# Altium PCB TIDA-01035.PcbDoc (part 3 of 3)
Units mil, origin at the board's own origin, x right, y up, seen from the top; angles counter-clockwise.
Board outline 3937.01 x 2952.76 mil, 4 copper layers (Top Layer, GND, PWR, Bottom Layer), stack 79.834 mil thick; 286 components, 165 nets, 861 pads, 352 vias.
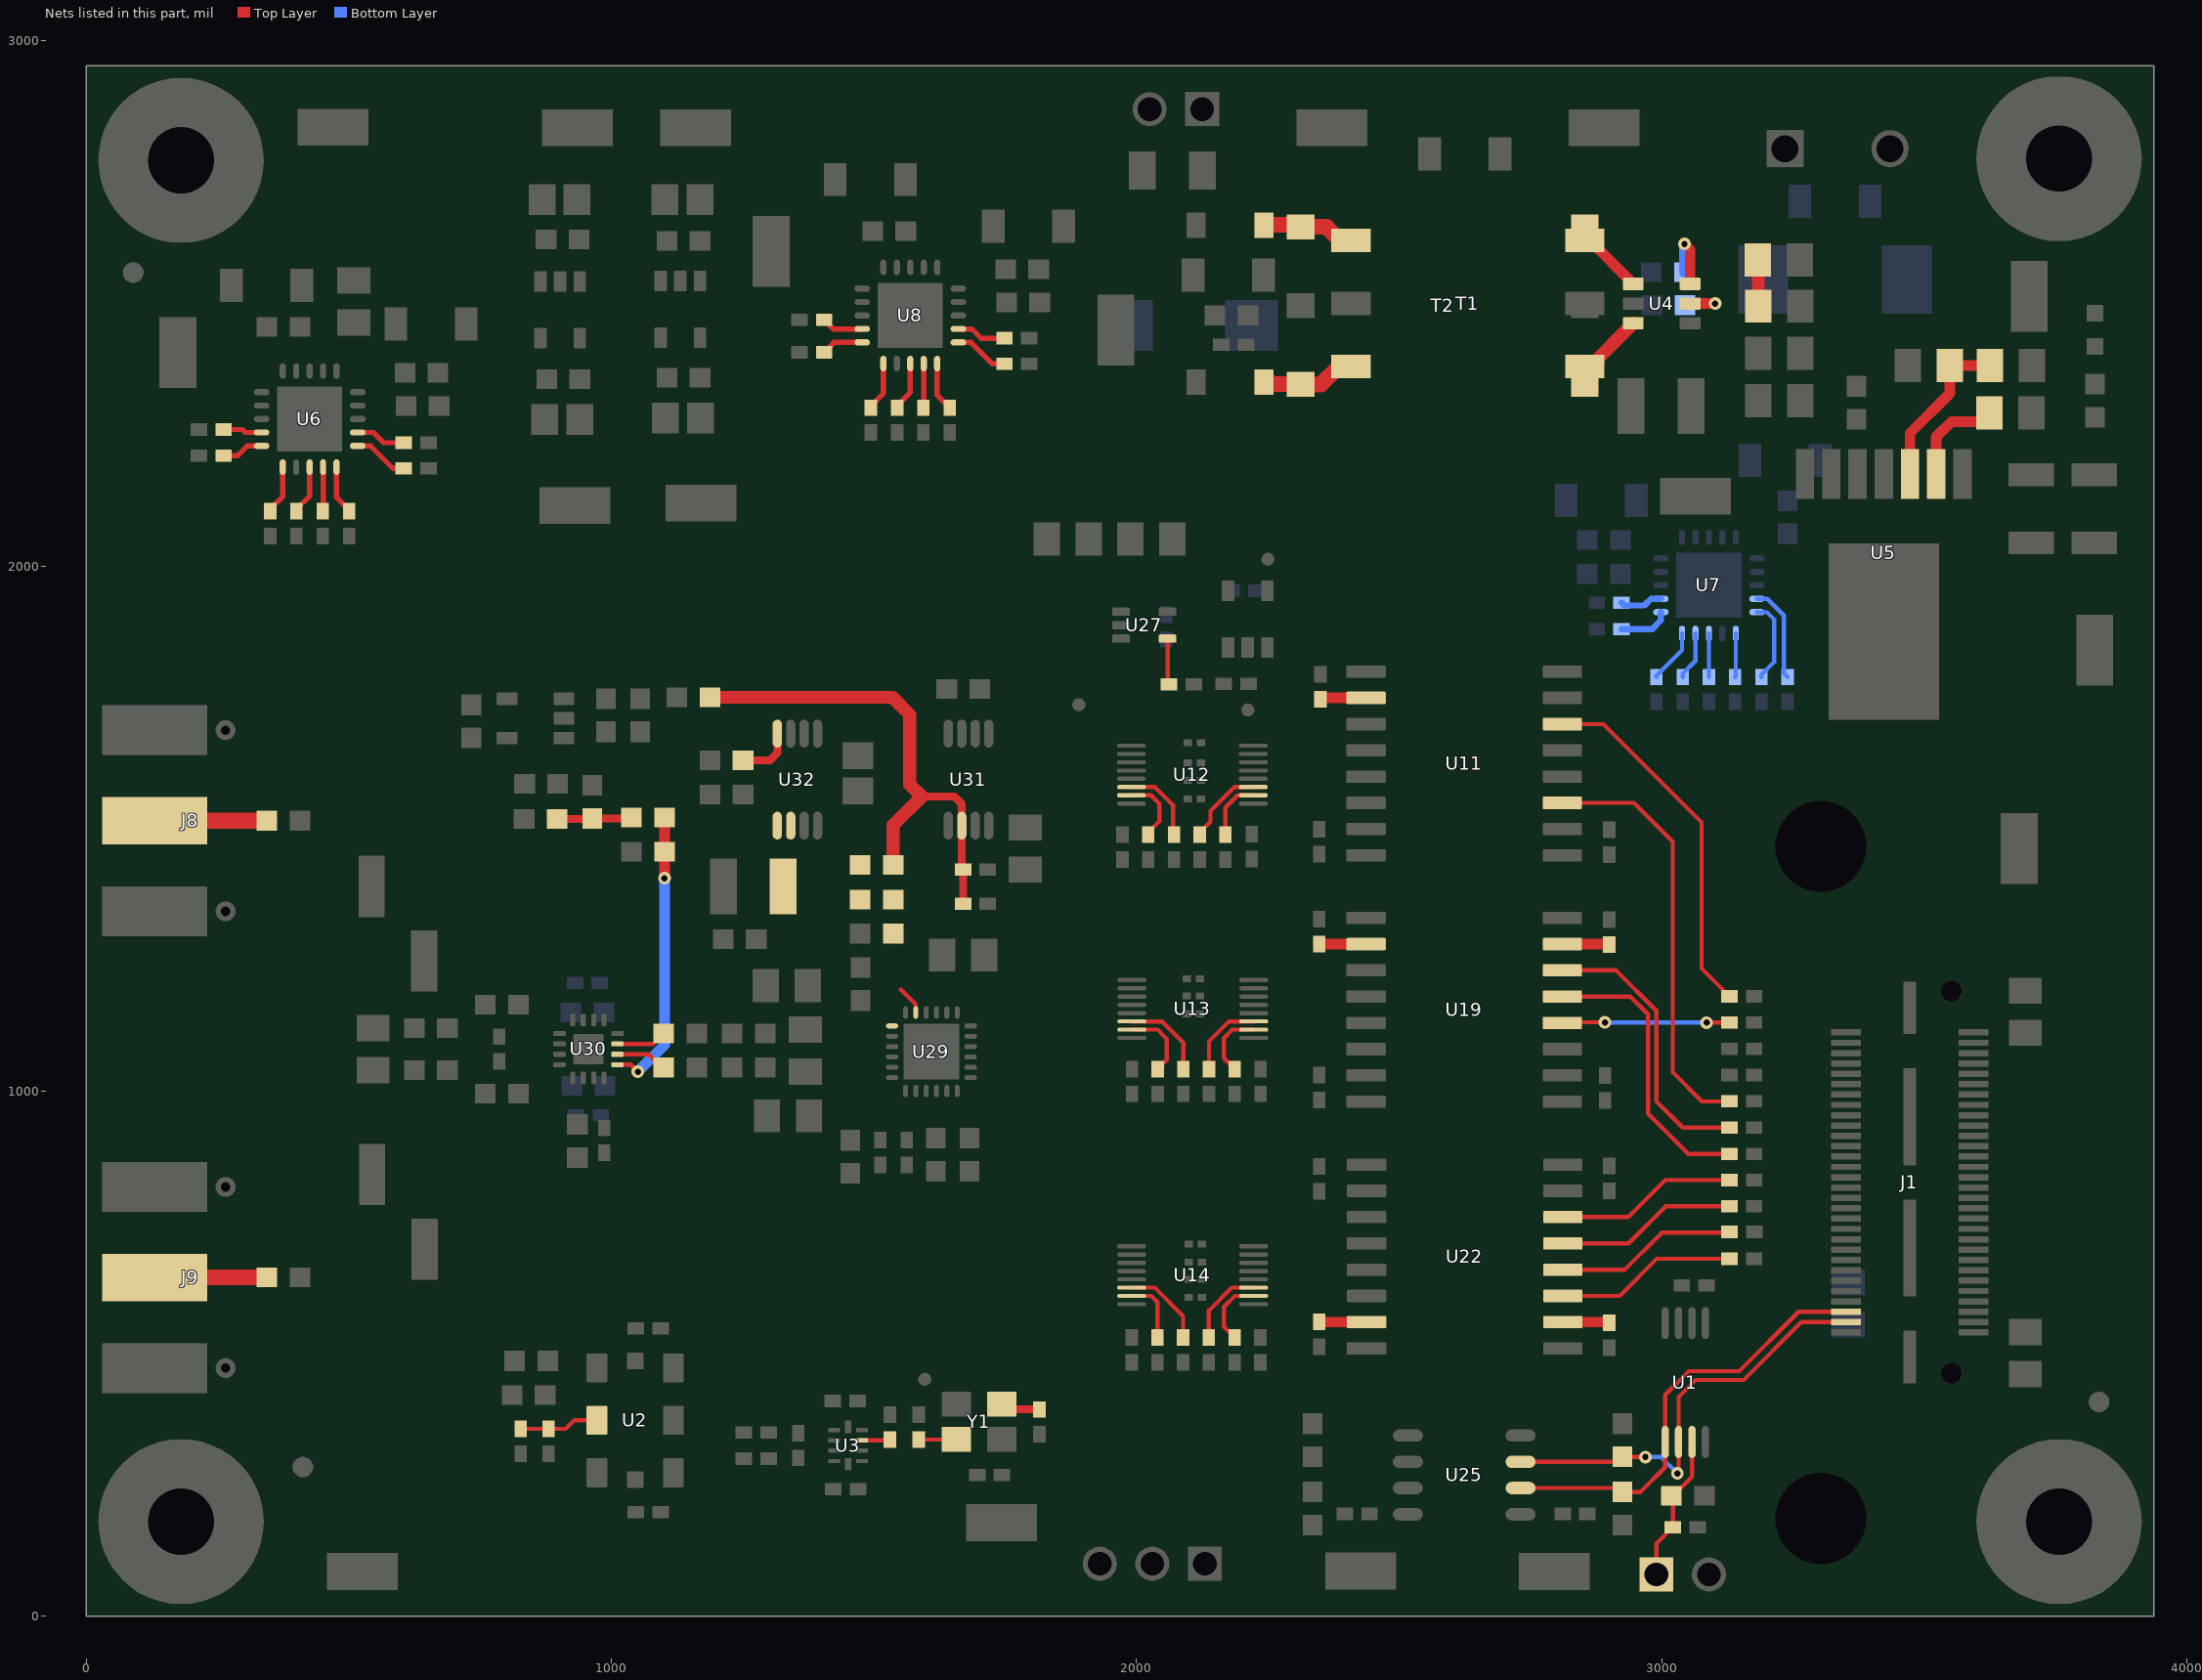
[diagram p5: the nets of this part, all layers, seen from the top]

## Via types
v1: diameter 24, hole 12, Top Layer to Bottom Layer, tented both sides, 324 vias
v2: diameter 19.68, hole 7.87, Top Layer to Bottom Layer, 24 vias
v3: diameter 32, hole 16, Top Layer to Bottom Layer, 4 vias

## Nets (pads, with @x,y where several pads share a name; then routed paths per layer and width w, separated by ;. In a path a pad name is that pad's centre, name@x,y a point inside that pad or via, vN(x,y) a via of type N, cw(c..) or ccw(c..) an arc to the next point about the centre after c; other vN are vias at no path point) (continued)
NetR13_1: R13.1 Y1.1 | length 75.8
  Top Layer w15: Y1.1@1753.15,393.62 R13.1@1815,393.62
  Top Layer w20: Y1.1@1743.31,403.46 Y1.1@1753.15,393.62
NetR14_1: R14.1 Y1.3 | length 71.8
  Top Layer w8: R14.1@1585,336.38 1656.54,336.38 Y1.3@1656.69,336.54
NetR17_1: R17.1 U3.8 | length 53.5
  Top Layer w8: U3.8@1477.09,334.84 1528.46,334.84 R17.1@1530,336.38
NetR18_1: R18.1 U12.3 | length 154.2
  Top Layer w8: R18.1@2120.18,1488.39 2120.18,1492.77 2140.68,1513.27 2140.68,1533.67 2186.16,1579.15 U12.3@2222.32,1579.15
NetR20_2: R20.2 R21.2 U2.2@972.17,373 | length 151.9
  Top Layer w8: R21.2@827,356.62 R20.2@880,356.62 912.62,356.62 929,373 U2.2@972.17,373
NetR24_1: R24.1 R34.2 U5.3 | length 288.9
  Top Layer w20: U5.3@3473,2175.63 3473,2253 3549,2329 R34.2@3549,2382 3597,2382 ; R34.2@3541,2382 R34.2@3541,2385
NetR26_1: R26.1 U5.2 | length 190.4
  Top Layer w20: U5.2@3523,2175.63 3523,2246 3552,2275 3607,2275 R26.1@3624,2292
NetR27_2: R27.2 U6.4 | length 74.8
  Top Layer w10: R27.2@261.06,2260.06 296.87,2260.06 302.46,2254.47 U6.4@333.53,2254.47
NetR28_2: R28.2 U6.5 | length 80.3
  Top Layer w10: R28.2@261.06,2210.06 287.27,2210.06 306.09,2228.88 U6.5@333.53,2228.88
NetR29_2: R29.2 U6.6 | length 94.1
  Top Layer w10: R29.2@350.06,2104.31 350.06,2108.85 373.88,2132.67 U6.6@373.88,2188.53
NetR30_2: R30.2 U6.8 | length 94.6
  Top Layer w10: R30.2@400.06,2104.31 400.06,2108.85 425.06,2133.85 U6.8@425.06,2188.53
NetR31_1: R31.1 R36.2 | length 88.7
  Top Layer w25: R36.2@3183.21,2583.35 3184,2582.56 R31.1@3184,2495
NetR32_2: R32.2 U6.9 | length 84.5
  Top Layer w10: R32.2@450.06,2104.31 450.65,2104.9 U6.9@450.65,2188.53
NetR33_2: R33.2 U6.10 | length 94.1
  Top Layer w10: U6.10@476.24,2188.53 476.24,2130.69 500.06,2106.87 R33.2@500.06,2104.31
NetR35_2: R35.2 U6.11 | length 105.6
  Top Layer w10: U6.11@516.6,2228.88 541.05,2228.88 583.87,2186.06 R35.2@604.44,2186.06
NetR37_2: R37.2 U6.12 | length 95.9
  Top Layer w10: U6.12@516.6,2254.47 546.46,2254.47 565.87,2235.06 R37.2@604.44,2235.06
NetR41_2: R41.2 U7.4 | length 184.9
  Bottom Layer w8: U7.4@3181.54,1937.76 3201.24,1937.76 3233,1906 3233,1795.62 R41.2@3240,1788.62
NetR42_2: R42.2 U8.4 | length 79.8
  Top Layer w10: R42.2@1405,2469.27 1422.59,2451.68 U8.4@1477.46,2451.68
NetR43_2: R43.2 U7.5 | length 158.2
  Bottom Layer w8: U7.5@3181.54,1912.17 3200.83,1912.17 3214,1899 3214,1817 3190,1793 R43.2@3190,1788.62
NetR44_2: R44.2 U8.5 | length 80.3
  Top Layer w10: R44.2@1405,2407.27 1423.82,2426.08 U8.5@1477.46,2426.08
NetR45_2: R45.2 U7.6 | length 83.7
  Bottom Layer w8: R45.2@3140,1788.62 3141.18,1789.8 U7.6@3141.18,1871.81
NetR46_2: R46.2 U8.6 | length 94.1
  Top Layer w10: R46.2@1494,2301.51 1494,2305 1517.82,2328.82 U8.6@1517.82,2385.73
NetR47_2: R47.2 U7.8 | length 83.2
  Bottom Layer w8: R47.2@3090,1788.62 U7.8@3090,1871.81
NetR48_2: R48.2 U8.8 | length 94.6
  Top Layer w10: R48.2@1544,2301.51 1544,2306 1569,2331 U8.8@1569,2385.73
NetR49_2: R49.2 U7.9 | length 93.3
  Bottom Layer w8: R49.2@3040,1788.62 3040,1795 3064.41,1819.41 U7.9@3064.41,1871.81
NetR50_2: R50.2 U8.9 | length 84.5
  Top Layer w10: R50.2@1594,2301.51 1594.59,2302.1 U8.9@1594.59,2385.73
NetR51_2: R51.2 U7.10 | length 103.4
  Bottom Layer w8: R51.2@2990,1788.62 2990,1791 3038.82,1839.82 U7.10@3038.82,1871.81
NetR52_2: R52.2 U8.10 | length 94.1
  Top Layer w10: U8.10@1620.18,2385.73 1620.18,2325.33 R52.2@1644,2301.51
NetR53_2: R53.2 U7.11 | length 97.4
  Bottom Layer w12: R53.2@2923.62,1880 2982,1880 2998.46,1896.46 U7.11@2998.46,1912.17
NetR54_2: R54.2 U8.11 | length 108.7
  Top Layer w10: U8.11@1660.54,2426.08 1684.92,2426.08 1726,2385 R54.2@1745.64,2385 ; R54.2@1748.38,2382.27 R54.2@1745.64,2385 ; R54.2@1748.38,2385 R54.2@1745.64,2385
NetR55_2: R55.2 U7.12 | length 82.2
  Bottom Layer w12: R55.2@2923.62,1930 2928.62,1925 2967,1925 2979.76,1937.76 U7.12@2998.46,1937.76
NetR56_2: R56.2 U8.12 | length 99
  Top Layer w10: U8.12@1660.54,2451.68 1686,2451.68 1703.68,2434 R56.2@1745.64,2434 ; R56.2@1748.38,2431.27 R56.2@1745.64,2434 ; R56.2@1748.38,2434 R56.2@1745.64,2434
NetR59_1: R59.1 U11.10 | length 88.1
  Top Layer w8: R59.1@2350,1746.38 R59.1@2352.62,1749
  Top Layer w20: R59.1@2352.62,1749 U11.10@2436.99,1749
NetR64_2: R64.2 U19.7 | length 89.2
  Top Layer w20: U19.7@2811.01,1280 2899.38,1280 R64.2@2900,1279.38
NetR65_1: R65.1 U19.10 | length 89.1
  Top Layer w20: R65.1@2348,1280.38 2348.38,1280 U19.10@2436.99,1280
NetR69_1: R69.1 U22.10 | length 88.6
  Top Layer w20: U22.10@2812.01,560 2898.62,560 R69.1@2900,558.62
NetR70_2: R70.2 U22.7 | length 90.2
  Top Layer w20: R70.2@2348,560.62 2348.62,560 U22.7@2437.99,560
NetR78_1: R78.1 U30.11 | length 97.3
  Top Layer w8: U30.11@1011.12,1089.84 1078.02,1089.84 1078.68,1089.18 R78.1@1099.5,1110
NetR84_1: R84.1 R85.2 U29.5 U29.7 | length 55.4
  Top Layer w8: 1551,1193 1551.48,1193 1579.54,1164.94 U29.5@1579.54,1149.74
NetR88_1: R88.1 U30.10 | length 98.8
  Top Layer w8: U30.10@1011.12,1070.16 1070.84,1070.16 1096,1045 R88.1@1099.5,1045
NetR94_2: R94.2 R95.2 R96.2 | length 142.8
  Top Layer w15: R94.2@896.5,1518 961.5,1518 R96.2@963,1519.5 1036.51,1519.5 R95.2@1038.01,1521
NetR100_2: R100.2 U32.4 | length 108
  Top Layer w15: R100.2@1250.56,1629.94 1301.94,1629.94 1315.68,1643.68 U32.4@1315.68,1680.88
NetR102_2: R102.2 U27.4 | length 88.1
  Top Layer w8: U27.4@2059,1861.82 2059,1777.87 R102.2@2061.96,1774.91
NetR103_1: R103.1 U4.5 | length 106.6
  Top Layer w20: U4.5@3054.13,2500 v1(3102,2500)
  Bottom Layer w20: R103.1@3044.5,2497 3047.5,2500 v1(3102,2500)
NetR104_2: R104.2 U4.6 | length 134
  Top Layer w20: v1(3043.5,2613.5) 3054.13,2602.86 U4.6@3054.13,2537.4
  Bottom Layer w20: R104.2@3043.5,2560 v1(3043.5,2613.5)
NetR105_1: R105.1 U12.2 | length 114.6
  Top Layer w8: R105.1@2169.18,1488.39 2169.18,1540.25 2192.33,1563.4 U12.2@2222.32,1563.4
NetR106_2: R106.2 U12.15 | length 127.7
  Top Layer w8: U12.15@1990.04,1563.4 2027.55,1563.4 2043.18,1547.77 2043.18,1513.77 2022.18,1492.77 R106.2@2022.18,1488.39
NetR107_2: R107.2 U12.14 | length 150.6
  Top Layer w8: U12.14@1990.04,1579.15 2034.8,1579.15 2069.24,1544.71 2069.24,1490.33 R107.2@2071.18,1488.39
NetR108_1: R108.1 U13.2 | length 131.2
  Top Layer w8: R108.1@2187.04,1042.02 2166.18,1062.88 2166.18,1100.85 2182.36,1117.03 U13.2@2223.18,1117.03
NetR109_2: R109.2 U13.15 | length 138.3
  Top Layer w8: U13.15@1990.9,1117.03 2039.92,1117.03 2057.18,1099.77 2057.18,1059.17 R109.2@2040.04,1042.02
NetR110_2: R110.2 U13.14 | length 165
  Top Layer w8: U13.14@1990.9,1132.78 2048.17,1132.78 2089.04,1091.91 R110.2@2089.04,1042.02
NetR111_2: R111.2 U13.3 | length 153.6
  Top Layer w8: R111.2@2138.04,1042.02 2138.04,1094.63 2176.19,1132.78 U13.3@2223.18,1132.78
NetR112_2: R112.2 U14.15 | length 121.3
  Top Layer w8: U14.15@1990.54,609.9 2028.05,609.9 2039.68,598.27 R112.2@2039.68,530.89
NetR113_2: R113.2 U14.14 | length 161
  Top Layer w8: U14.14@1990.54,625.65 2034.3,625.65 2088.68,571.27 R113.2@2088.68,530.89
NetR114_2: R114.2 U14.2 | length 131.8
  Top Layer w8: R114.2@2186.68,530.89 2166.18,551.39 2166.18,588.85 2187.23,609.9 U14.2@2222.82,609.9
NetR115_2: R115.2 U14.3 | length 154.5
  Top Layer w8: R115.2@2137.68,530.89 2137.68,582.27 2181.06,625.65 U14.3@2222.82,625.65
NISO_SCL: J1.58 R74.1 U1.6 U25.3 | length 839.8
  Top Layer w8: U25.3@2731.28,294 2915.5,294 R74.1@2925,303.5 2968.5,303.5 v1(2969,303) ; v1(3030,272) 3032.2,274.2 U1.6@3032.2,331.81 3032.2,417.2 3065,450 3156,450 3266.15,560.15 J1.58@3351,560.15
  Bottom Layer w8: v1(2969,303) 2999,303 v1(3030,272)
NISO_SDA: J1.56 R72.1 U1.5 U25.2 | length 845.9
  Top Layer w8: U25.2@2731.28,244 2917.5,244 R72.1@2925,236.5 2959.5,236.5 3006.61,283.61 U1.5@3006.61,331.81 3006.61,421.61 3051.65,466.65 3147.65,466.65 3260.85,579.85 J1.56@3351,579.85
REFIN_ADS8900B: R90.1 R93.2 R97.2 R98.1 U31.6 | length 976.1
  Top Layer w15: 1591,1561 1653,1561 1667.06,1546.94 U31.6@1667.06,1505.68 1667.06,1424.32 R93.2@1669.38,1422 R90.1@1669.38,1357
  Top Layer w25: R97.2@1187.5,1750 1535,1750 1568,1717 1568,1584 1591,1561 1536.5,1506.5 R98.1@1536.5,1440
REFIN_ADS9110: C98.2 R84.2 R98.2 U32.5 U32.6
RVS: R8.1 U19.5 | length 552.8
  Top Layer w8: U19.5@2811.01,1180 2940.37,1180 2974,1146.37 2974,957 3050.45,880.55 R8.1@3128.88,880.55
SCLK: R5.1 U11.3 | length 810.5
  Top Layer w8: U11.3@2811.01,1549 2947,1549 3021,1475 3021,1036 3076.45,980.55 R5.1@3128.88,980.55
SDI: R2.1 U19.4 | length 318.5
  Top Layer w8: U19.4@2811.01,1130 2812.01,1131 v1(2892,1131) ; v1(3085.55,1130.55) R2.1@3128.88,1130.55
  Bottom Layer w8: v1(2892,1131) 2892.45,1130.55 v1(3085.55,1130.55)
SDO0: R9.1 U22.14 | length 346.1
  Top Layer w8: U22.14@2812.01,760 2936,760 3006.55,830.55 R9.1@3128.88,830.55
SDO1: R10.1 U22.13 | length 346.1
  Top Layer w8: U22.13@2812.01,710 2937,710 3007.55,780.55 R10.1@3128.88,780.55
SDO2: R11.1 U22.12 | length 346.1
  Top Layer w8: U22.12@2812.01,660 2930,660 3000.55,730.55 R11.1@3128.88,730.55
SDO3: R12.1 U22.11 | length 346.1
  Top Layer w8: U22.11@2812.01,610 2920,610 2990.55,680.55 R12.1@3128.88,680.55
SRESETN: R1.1 U11.6 | length 695.8
  Top Layer w8: U11.6@2811.01,1699 2889,1699 3076,1512 3076,1233.42 R1.1@3128.88,1180.55
SYSCLK: R7.1 U19.6 | length 542.9
  Top Layer w8: U19.6@2811.01,1230 2913,1230 2990,1153 2990,980.63 3040.08,930.55 R7.1@3128.88,930.55
TX1: T1.1 T2.1 U4.3 | length 126.5
  Top Layer w25: T1.1@2853.64,2379.92 2863.19,2379.92 U4.3@2945.87,2462.6
TX3: T1.3 T2.3 U4.1 | length 126.5
  Top Layer w20: T1.3@2853.64,2620.08 2863.19,2620.08 U4.1@2945.87,2537.4
TX4: D3.2 T1.4 T2.4 | length 181.9
  Top Layer w30: D3.2@2242.47,2650.35 T2.4@2317.79,2650.35 ; T2.4@2312.53,2646 2362,2646 2387.92,2620.08 T1.4@2408.36,2620.08
TX6: D1.2 T1.6 T2.6 | length 167.1
  Top Layer w30: D1.2@2255.26,2350.35 2259.26,2346.35 T2.6@2310.79,2346.35 ; T2.6@2312.53,2346 2351,2346 2384.92,2379.92 T1.6@2408.36,2379.92
VIN+: J9.1 R86.1 | length 213.5
  Top Layer w30: J9.1@130,645 R86.1@343.5,645
VIN-: J8.1 R80.1 | length 213.5
  Top Layer w30: J8.1@130,1515 R80.1@343.5,1515
VOCM: C100.1 R95.1 U30.9 | length 549.6
  Top Layer w8: U30.9@1011.12,1050.47 1036.53,1050.47 v1(1050,1037)
  Top Layer w15: v1(1100.94,1405.43) v1@1101,1405.5
  Top Layer w20: v1@1101,1405.5 C100.1@1101,1456 R95.1@1101,1521
  Bottom Layer w20: v1(1050,1037) 1100.94,1087.94 v1(1100.94,1405.43)
WP1: C3.2 J2.1 R6.1 U1.7 | length 284.5
  Top Layer w8: J2.1@2990,79.5 2990,138.12 C3.2@3021.38,169.5 3021.38,226.63 R6.1@3018.5,229.5 3021.44,229.5 3057.8,265.85 U1.7@3057.8,331.81
pads on no net: FID1.1 FID2.1 FID3.1 FID4.1 FID5.1 FID6.1 H1.1 H2.1 H3.1 H4.1 H5.0 H6.0 H7.0 H8.0 H13. H14. J1.2 J1.3 J1.4 J1.5 J1.6 J1.7 J1.8 J1.9 J1.10 J1.11 J1.12 J1.13 J1.14 J1.15 J1.17 J1.19 J1.21 J1.23 J1.25 J1.26 J1.27 J1.29 J1.31 J1.33 J1.35 J1.36 J1.37 J1.39 J1.41 J1.43 J1.45 J1.46 J1.47 J1.48 J1.49 J1.51 J1.52 J1.53 J1.54 J1.55 J1.57 J1.MH1 J1.MH2 U2.1@972.17,457.25 U2.1@972.17,488.75 U2.2@972.17,357.25 U2.2@972.17,388.75 U2.3@972.17,257.25 U2.3@972.17,288.75 U2.4@1117.83,257.25 U2.4@1117.83,288.75 U2.5@1117.83,357.25 U2.5@1117.83,388.75 U2.6@1117.83,457.25 U2.6@1117.83,488.75 U3.4 U3.6 U3.9 U6.2 U6.17 U6.18 U6.19 U7.2 U7.17 U7.18 U7.19 U8.2 U8.17 U8.18 U8.19 U9.3 U9.4 U10.3 U10.4 U11.7 U13.5 U13.12 U19.3 U19.14 U21.1 U29.6 U31.1 U31.3 U31.5 U31.7 U31.8

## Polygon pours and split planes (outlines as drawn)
NetC13_1 on Top Layer "Top Layer-No Net" (solid, pour order 63): 2091.79,2903.35 2091.79,2614.35 2081.79,2604.35 1929.79,2604.35 1916.79,2591.35 1916.79,2314.35 1925.79,2305.35 2164.79,2305.35 2170.79,2311.35 2170.79,2474.35 2169.79,2475.35 2169.79,2907.35 2158.79,2918.35 2099.79,2918.35 2091.79,2910.35
AGND_ISO on Top Layer "Top Layer-No Net" (solid, remove dead copper, pour order 71): 1512,1053 1546,1053 1549,1050 1549,1040 1545,1036 1517,1036 1492,1011 1420,939 1420,911 1420,824 1413,817 1353,817 1348,822 1348,989 1352,993 1412,993 1419,1000 1419,1043 1429,1053
NetC80_1 on Top Layer "Top Layer-No Net" (solid, remove dead copper, pour order 67): 1598,971 1637,932 1637,911 1637,895 1633,891 1545,891 1543,893 1543,967 1547,971
REFIN_ADS9110 on Top Layer "Top Layer-No Net" (solid, remove dead copper, pour order 59): 1493,1455 1493,1338 1490,1335 1302,1335 1300,1335 1291,1344 1291,1535.18 1294.96,1539.13 1342.26,1539.13 1347.15,1534.24 1347.15,1462.85 1352,1458 1490,1458
AGND_ISO on Top Layer "Top Layer-No Net" (solid, remove dead copper, pour order 53): 1570,1260 1570,1453 1579,1462 1613,1462 1632,1462 1636,1458 1636,1343 1648.81,1330.19 1655,1324 1655,1259
NetC88_1 on Top Layer "Top Layer-No Net" (solid, remove dead copper, pour order 51): 1687,1294 1687,1222 1680,1215 1643,1215 1632,1204 1612,1184 1612,1169 1612,1141 1615,1138 1622,1138 1627,1143 1627,1177 1635,1185 1637,1187 1663,1187 1730,1187 1744,1201 1744,1376.87 1742.21,1378.65 1701.65,1378.65 1699,1376 1699,1307 1687,1295
AGND_ISO on Top Layer "Top Layer-No Net" (solid, remove dead copper, pour order 48): 1585,1331 1648,1331 1655,1324 1655,1222 1654,1221 1621,1221 1607,1207 1604,1204 1604,1161 1604,1144 1599,1139 1595,1139 1592,1142 1592,1180 1578,1194 1571,1201 1571,1321 1581,1331
NetR84_1 on Top Layer "Top Layer-No Net" (solid, remove dead copper, pour order 47): 1544,1119 1517,1119 1515,1121 1515,1292 1515,1390 1518.54,1393.54 1552.46,1393.54 1556,1390 1556,1194 1585,1165 1585,1139 1582,1136 1548,1136 1550,1136 1547,1133 1547,1119
DVDD_ISO on Top Layer "Top Layer-No Net" (solid, remove dead copper, pour order 44): 1881.18,2122.77 1881.18,1976.77 1891.18,1966.77 2011.18,1966.77 2018.18,1973.77 2018.18,2119.77 2011.18,2126.77 1885.18,2126.77 1881.18,2122.77
AGND_ISO on Top Layer "Top Layer-No Net" (solid, remove dead copper, pour order 82): 1543,1097 1433,1097 1418,1112 1418,1155 1412,1161 1349,1161 1341,1169 1341,1286 1351,1296 1407,1296 1438,1265 1438,1200 1440,1198 1498,1198 1506,1190 1506,1118 1510,1114 1513,1111 1546,1111 1546,1099 1544,1097
LDO_IN_ISO on Top Layer "Top Layer-No Net" (solid, pour order 68): 1776,2681 1776,2776 1794,2794 1807,2807 1808,2807 1593,2807 1616,2784 1616,2681
LDO_IN_ISO on Top Layer "Top Layer-No Net" (solid, pour order 66): 1214,2790 1919,2790 1919,2698 1929,2688 2042,2688 2058,2704 2058,2918 597,2918 564,2885 564,2508.5 555.5,2500 553,2497.5 553,2483 631,2483 631,2773 643,2785 647,2789 904,2789
AGND_ISO on Top Layer "Top Layer-No Net" (solid, pour order 60): 2191,2409 2201,2399 2347,2399 2350,2402 2350,2428 2352,2430 2448,2430 2449,2431 2449,2572 2440,2581 2201,2581 2191,2571
AGND_ISO on Top Layer "Top Layer-No Net" (solid, remove dead copper, pour order 57): 635,2228 635,2081 627,2073 484,2073 239,2073 232,2080 229,2083 229,2227 229,2277 223,2283 130,2283 120,2273 120,2004 133,1991 711,1991 728,1991 740,2003 749,2012 749,2473 749,2496 745,2500 657,2500 651,2494 651,2268 635,2252
LDO_IN_ISO on Top Layer "Top Layer-No Net" (solid, pour order 56): 468,2489 468,2358 471,2355 497,2355 499,2353 502,2350 502,2329 502,2323 504,2321 558.52,2321 577.04,2339.52 626.52,2339.52 631,2344 631,2489.87 620.64,2500.23 472.23,2500.23 468,2496
5V_ISO on Top Layer "Top Layer-No Net" (solid, remove dead copper, pour order 55): 363.62,2483.86 126.07,2483.86 117.07,2474.86 117.07,2339.86 117.07,2315.86 127.07,2305.86 274.07,2305.86 304.07,2275.86 309.07,2270.86 339.07,2270.86 344.07,2270.86 348.07,2274.86 348.07,2357.86 351.07,2360.86 379.07,2360.86 381.07,2362.86 381.07,2411.86 368.07,2424.86 368.07,2468.86 368.07,2479.41
AGND_ISO on Top Layer "Top Layer-No Net" (solid, remove dead copper, pour order 54): 1793,2485 1793,2679.64 1800,2686.64 1887.36,2686.64 1892,2682 1892,2208 1875,2191 1314,2191 1303,2202 1297,2208 1297,2478 1297,2485 1303,2491 1369,2491 1374,2486 1374,2273 1377,2270 1510,2270 1770,2270 1774,2274 1780,2280 1780,2396 1780,2451 1786,2457 1793,2464 1793,2484
3P3V_ISO on Top Layer "Top Layer-No Net" (solid, remove dead copper, pour order 50): 1524,2668 1524,2555 1520,2551 1497,2551 1493,2547 1493,2519 1493,2475 1489,2471 1442,2471 1434,2479 1434,2513 1427,2520 1260,2520 1255,2525 1255,2665 1272,2682 1510,2682
LDO_IN_ISO on Top Layer "Top Layer-No Net" (solid, pour order 46): 1776,2594 1776,2545 1771,2540 1734.55,2540 1724.02,2529.47 1714.55,2520 1661,2520 1648,2520 1646,2522 1646,2554 1645,2555 1616,2555 1616,2681 1623,2688 1770,2688 1776,2682
5V_ISO on Top Layer "Top Layer-No Net" (solid, pour order 45): 994,1031 994,1023 994,996 996,994 999,991 1008,991 1034,991 1039,986 1039,919 1035,915 879,915 874,920 874,982 881,989 883,991 917,991 920,994 920,1033 922.2,1035.2 989.8,1035.2
AGND_ISO on Top Layer "Top Layer-No Net" (solid, pour order 43): 918,1129 918,1137 918,1164 916,1166 913,1169 904,1169 878,1169 873,1174 873,1241 877,1245 1033,1245 1038,1240 1038,1178 1031,1171 1029,1169 995,1169 992,1166 992,1127 989.8,1124.8 922.2,1124.8
5VDC on Top Layer "Top Layer-No Net" (solid, pour order 72): 3021,2359 3021,2242 3012,2233 2910,2233 2901,2224 2901,2088 2906,2083 3285,2083 3289,2087 3292,2090 3292,2140 3292,2229 3288,2233 3221,2233 3213,2241 3213,2321 3214,2322 3214,2440 3209,2445 3139,2445 3134,2440 3134,2382 3122,2370 3025,2370 3021,2366
+12VDC on Top Layer "Top Layer-No Net" (solid, pour order 73): 3552,2598 3741,2598 3750,2589 3750,2239 3873,2239 3882,2230 3882,2128 3875,2121 3559,2121 3556,2124 3555,2125 3555,2136 3555,2232 3562,2239 3675,2239 3675,2435 3561,2435 3543,2453 3543,2589
GND on Top Layer "Top Layer-No Net" (solid, remove dead copper, pour order 78): 3879.12,2076.11 3321.11,2076.11 3308,2063 3308,1707 3317,1698 3862,1698 3879.12,1715.12 3879.12,2076.11
GND on Top Layer "Top Layer-No Net" (solid, remove dead copper, pour order 77): 3547,2660 3359,2660 3351,2668 3351,2862 3366,2877 3368,2879 3383,2879 3538,2879 3557,2860 3557,2670
GND on Top Layer "Top Layer-No Net" (solid, remove dead copper, pour order 49): 3404,2224 3404,2080 3400,2076 3321,2076 3308,2063 3308,1707 3317,1698 3862,1698 3879.12,1715.12 3879.12,2067.88 3872,2075 3871,2076 3853,2076 3452,2076 3446,2082 3443,2085 3443,2149 3443,2258 3486,2301 3501,2316 3501,2395 3501,2579 3557,2635 3557,2670 3557,2860 3540,2877 3366,2877 3351,2862 3351,2645 3344,2638 3237,2638 3231,2632 3231,2547 3233,2545 3288,2545 3298,2535 3307,2526 3307,2480 3307,2280 3312,2275 3383,2275 3403,2255
AGND_ISO on Bottom Layer "Top Layer-No Net" (solid, pour order 61): 2168.79,2514.35 2168.79,2403.35 2175.79,2396.35 2386.35,2396.35 2393,2403 2393,2574 2385.65,2581.35 2178.79,2581.35 2168.79,2571.35
NetC13_1 on Bottom Layer "Top Layer-No Net" (solid, pour order 64): 2020.79,2604.35 1929.79,2604.35 1916.79,2591.35 1916.79,2379.35 1924.79,2371.35 2038.79,2371.35 2041.79,2374.35 2041.79,2598.35 2035.79,2604.35
5VDC on Bottom Layer "Top Layer-No Net" (solid, pour order 70): 3011,2011 2971,2011 2960.54,2021.46 2900,2021.46 2900,2364 3137,2364 3137,2254 3114,2231 3114,2091 3110,2087 3047,2087 3042,2082 3042,2042 3015,2042 3011,2038
+12VDC on Bottom Layer "Top Layer-No Net" (solid, pour order 74): 3420,2636 3614,2636 3627,2623 3627,2488 3616,2477 3422,2477 3413,2486 3413,2629
+12VDC_IN on Bottom Layer "Top Layer-No Net" (solid, pour order 75): 3170,2879 3292,2879 3301,2870 3301,2488 3288,2475 3141,2475 3132,2484 3132,2870 3141,2879
3P3V on Bottom Layer "Top Layer-No Net" (solid, remove dead copper, pour order 79): 3140,2080 3324,2080 3328,2076 3328,1968 3320,1960 3309,1949 3179,1949 3166,1962 3166,2040 3163,2043 3138,2043 3135,2046 3135,2077 3138,2080
GND on Bottom Layer "Top Layer-No Net" (solid, remove dead copper, pour order 80): 3352,2071 3352,1702 3357,1697 3861,1697 3879.12,1715.12 3879.12,2076.11 3357.81,2076.11 3353,2071.3
GND on Bottom Layer "Top Layer-No Net" (solid, remove dead copper, pour order 81): 2877,1984 2877,2157 2866,2168 2801,2168 2794,2161 2794,1687 2810,1671 3249,1671 3262,1684 3262,1749 3256,1755 3255,1756 3209,1756 2924,1756 2916,1764 2916,1829 2896,1849 2890,1855 2890,1920 2890,1953 2877,1966
GND on Bottom Layer "Top Layer-No Net" (solid, pour order 76): 3547,2660 3359,2660 3351,2668 3351,2862 3366,2877 3368,2879 3383,2879 3538,2879 3557,2860 3557,2670
GND on GND "Top Layer-No Net" (solid, remove dead copper, pour order 84): 2775,2892 2775,382 2763,370 2710.36,370 2700.85,360.49 2700.85,40.15 2706,35 3885,35 3904,54 3904,2886 3865,2925 2808,2925
AGND_ISO on GND "Top Layer-No Net" (solid, remove dead copper, pour order 83): 2476,2899 2454,2921 64,2921 30,2887 30,71 71,30 2532.65,30 2547.31,44.65 2547.31,362.69 2541,369 2478,369 2476,371
3P3V_ISO on PWR "Top Layer-No Net" (solid, remove dead copper, pour order 52): 2476,60 2453,37 396,37 386,47 386,555 409,578 1664,578 1674,568 1674,436 1686,424 2020,424 2071,475 2071,2177 2058,2190 1381,2190 1263,2190 1253,2200 1253,2688 1253,2897 1277,2921 2452,2921 2476,2897
5V_ISO on PWR "Top Layer-No Net" (solid, remove dead copper, pour order 58): 1342,2169 1657,2169 1675,2151 1675,622 1652,599 397,599 364,566 364,419 355,410 47,410 30,427 30,2891 55,2916 1213,2916 1232,2897 1232,2179 1242,2169
3P3V on PWR "Top Layer-No Net" (solid, remove dead copper, pour order 62): 3878,2097 2806,2097 2776,2067 2772,2063 2772,1847 2772,53 2785,40 3872,40 3904,72 3904,2071
5VDC on PWR "Top Layer-No Net" (solid, remove dead copper, pour order 65): 2890,2120 2782,2120 2772,2130 2772,2889 2808,2925 3871,2925 3904,2892 3904,2146 3878,2120
DVDD_ISO on PWR "Top Layer-No Net" (solid, remove dead copper, pour order 69): 1705,2161 2041,2161 2050,2152 2050,486 2010,446 1709,446 1696,459 1696,996 1696,2152

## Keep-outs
GND:
  lines w20: 30,375 453,375 812,734 1712,734 1746,768 1746,867 1651,962 1651,988 ; 33,1935 1632,1935 1827,1740 1827,1378 1649,1200 1649,1178 1649,1162
Keep-Out Layer:
  pour cut-out: 2547.31,370 2478,370 2478,2706 2477,2707 2585,2707 2585,2767 2584,2768 2584,2918 2669,2918 2669,2707 2772,2707 2772,370 2695.89,370 2695.89,37.11 2547.31,37 2547.31,52.31
  text ".Layer_Name" at -165.1,-2129.89 h60

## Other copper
Top Layer:
  text ".layer_Name" at -150.1,-2119.39 h60
GND:
  text ".layer_Name" at -127,-2122 h60
PWR:
  pour cut-out: 1525.54,1162.54 1675,1162.54 1675,993 1524.66,993 1521.46,996.2 1521.46,1158.46
  text ".layer_Name" at -154,-2131 h60
Bottom Layer:
  text ".Layer_Name" at -91.1,-2129.39 h60
Multi-Layer:
  pour cut-out: 793,1192.98 857.97,1192.98 858.7,1123.31 922.22,1123.31 922.52,1041.52 861.67,1041.52 858,1037.85 858,961 793,961 793,1025 763,1025 763,1129.01 793,1129.01
  pour cut-out: 992.42,1099.42 992,1099 992,1061.3 1066.59,1061.3 1066.59,1017.8 1132,1017.8 1132,1141.42 1067,1141.42 1067,1099.42

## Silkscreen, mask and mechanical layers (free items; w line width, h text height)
Top Overlay:
  circle w6: c2212,1726 r22
  circle w6: c2369.48,1882.48 r26
  circle w6: c2250,2013 r22
  circle w6: c2250.71,2235 r26
  circle w6: c1890,1736 r22
  circle w6: c1733.02,1892.98 r26
  circle w10: c3090,2650 r14.32
  circle w6: c1596.64,673 r26
  circle w6: c1596.64,451 r18.36
  lines w6: 1380,385 1396,369 1405.93,369 ; 1853,2525 1863,2525 ; 1923,622 1941,622 ; 1929,660 1943,660 ; 1930,581 1943,581 ; 1930,701 1945,701 ; 1936,1135 1944,1135 ; 1936,1570 1946,1570 ; 1937,1610 1946,1610 ; 1938,1538 1950,1538 ; 1939,1173 1947,1173 ; 1940,1212 1948,1212 ; 1941.95,1653 1948,1653 ; 2038,1590 2069,1590 ; 2039,1662 2070,1662 ; 2040,1626 2071,1626 ; 2041,1556 2072,1556 ; 2045,706 2076,706 ; 2046,606 2077,606 ; 2046,640 2077,640 ; 2046,674 2077,674 ; 2046,1145 2077,1145 ; 2046,1180 2077,1180 ; 2046,1213 2077,1213 ; 2097.98,1166.75 2109.98,1166.75 ; 2097.98,1193.3 2109.98,1193.3 ; 2099.36,1134.13 2111.36,1134.13 ; 2099.36,1160.67 2111.36,1160.67 ; 2099.36,1201.13 2111.36,1201.13 ; 2099.36,1227.67 2111.36,1227.67 ; 2101.5,1543.5 2113.5,1543.5 ; 2101.5,1570.04 2113.5,1570.04 ; 2101.5,1578.5 2113.5,1578.5 ; 2101.5,1605.04 2113.5,1605.04 ; 2101.5,1612.5 2113.5,1612.5 ; 2101.5,1639.04 2113.5,1639.04 ; 2101.5,1650.5 2113.5,1650.5 ; 2101.5,1677.04 2113.5,1677.04 ; 2103,594 2115,594 ; 2103,620.54 2115,620.54 ; 2103,628 2115,628 ; 2103,654.54 2115,654.54 ; 2103,661 2115,661 ; 2103,687.54 2115,687.54 ; 2103,695 2115,695 ; 2103,721.54 2115,721.54 ; 2134,1816 2141.58,1808.42 2141.58,1796.41 ; 2243,1725 2272,1725 ; 2265,58 2337,58 ; 2843,302 2886,259 2897.8,259
  text "AGND_ISO" at 364,2900 h30
  text "LDO_IN_ISO" at 913,2897 h30
  text "GND" at 2846,2894 h30
  text "AGND_ISO" at 2270,2893 h30
  text "GND" at 3597,2851 h30 r90
  text "+12VDC_IN" at 3076,2693 h30 r90
  text "3P3V_ISO" at 1243,2495 h30 r90
  text "+12VDC" at 3635,2442 h30 r90
  text "5V_ISO" at 109,2321 h30 r90
  text "AGND_ISO" at 1989,2227 h30
  text "5VDC" at 3019,2038 h30
  text "A1P8V_ISO" at 1084,2025 h30
  text "1P8V_ISO" at 813,2024 h30
  text "ADC CONVSTn" at 2287,2001 h30
  text "AGND_ISO" at 2401,1905 h30
  text "AGND_ISO" at 1467,1898 h30
  text "VIN-" at 123,1811 h30
  text "GND" at 3790,1719 h30
  text "ADC CONVST1" at 1856,1694 h30 r90
  text "ADC CONVST" at 2313,1570 h30 r90
  text "3P3V" at 3614,1415 h30 r90
  text "SRESETN" at 2892,1186.23 h30
  text "SDI" at 3023,1115 h30
  text "CONVST" at 2928,1067 h30
  text "CSN" at 3013,1017 h30
  text "SCLK" at 2981,967 h30
  text "VIN+" at 105,956 h30
  text "SYSCLK" at 2921,916 h30
  text "RVS" at 3014,869 h30
  text "SDO0" at 2983,819 h30
  text "SDO1" at 2985,767 h30
  text "SDO2" at 2985,715 h30
  text "SDO3" at 2984,666 h30
  text "PHI INTERFACE" at 3785,650 h30 r90
  text "AGND_ISO" at 1569,604 h30
  text "ADC_SYSCLK" at 1493,528 h30
  text "GND" at 2620,100 h30
  text "DVDD_ISO" at 1628,92 h30
  text "AGND_ISO" at 622,72 h30
  text "TIDA-01035-E1" at 980,54 h40
  text "AGND_ISO" at 2251,30 h30 r90
  text ".layer_Name" at -124.1,-2117.39 h60
Bottom Overlay:
  text ".Layer_Name" at -165.1,-2129.89 h60
Top Paste:
  text ".Layer_Name" at -177.1,-2132.89 h60
Bottom Paste:
  text ".Layer_Name" at -177.1,-2132.89 h60
Top Solder:
  text ".Layer_Name" at -149.1,-2140.39 h60
Bottom Solder:
  text ".Layer_Name" at -102.1,-2136.39 h60
M1 Board Outline:
  the board outline again, w20
M2 Board Dimensions:
  rectangle: -147.6,-1276.39 227.4,-1151.39
  lines w7: -147.6,-1276.39 -147.6,-1026.39 ; -22.6,-1276.39 -22.6,-1026.39 ; 227.4,-1276.39 227.4,-1026.39 ; 477.4,-1276.39 477.4,-1026.39 ; -272.6,-1276.39 -272.6,-1026.39 727.4,-1026.39 727.4,-1276.39 -272.6,-1276.39
  lines w10: -272.6,-1341.39 -272.6,-1321.39 ; -212.6,-1351.39 -272.6,-1331.39 ; -212.6,-1311.39 -272.6,-1331.39 ; -48.52,-1331.39 -272.6,-1331.39 ; 503.32,-1331.39 727.4,-1331.39 ; 667.4,-1351.39 727.4,-1331.39 ; 667.4,-1311.39 727.4,-1331.39 ; 727.4,-1341.39 727.4,-1321.39
  text "1000 (mil)" at -38.52,-1367.38 h60
M3 3D STEP Top:
  text ".Layer_Name" at -165.1,-2129.89 h60
M4 3D STEP Bottom:
  text ".Layer_Name" at -165.1,-2129.89 h60
M5 Assembly Top:
  circle w10: c2121.79,2868.35 r14.87
  circle w10: c1169,2567 r8.25
  circle w10: c938,2566 r8.25
  circle w10: c928,1671 r7.62
  circle w10: c3588,2092 r18.68
  circle w10: c2990,80 r18.44
  circle w10: c2125,100 r12.17
  circle w10: c2181,596 r6.71
  circle w10: c2182,1101 r6.08
  circle w10: c2180,1549 r7.07
  lines w6: 2025,676 2067,676 ; 2025,704 2067,704 ; 2026,644 2068,644 ; 2027,601 2069,601 ; 2027,1143 2069,1143 ; 2027,1212 2069,1212 ; 2028,1182 2070,1182 ; 2028,1589 2070,1589 ; 2028,1660 2070,1660 ; 2029,1556 2071,1556 ; 2030,1628 2072,1628 ; 2528,2216 2528,2248 ; 2627,2587 2627,2658 ; 2067,676 2061,670 2061,682 2067,676 ; 2067,704 2061,710 2061,698 2067,704 ; 2068,644 2062,638 2062,650 2068,644 ; 2069,601 2063,595 2063,607 2069,601 ; 2069,1143 2063,1137 2063,1149 2069,1143 ; 2069,1212 2063,1206 2063,1218 2069,1212 ; 2070,1182 2064,1176 2064,1188 2070,1182 ; 2070,1589 2064,1583 2064,1595 2070,1589 ; 2070,1660 2064,1654 2064,1666 2070,1660 ; 2071,1556 2065,1550 2065,1562 2071,1556 ; 2072,1628 2066,1622 2066,1634 2072,1628 ; 2528,2248 2520,2240 2536,2240 2528,2248 ; 2627,2658 2618,2649 2636,2649 2627,2658
  lines w12: -1034.1,-2201.56 5565.9,-2201.56 ; -1034.1,-1998.23 5567.9,-1998.23 ; -1034.1,-1794.89 -1034.1,-2404.89 2970.9,-2404.89 5567.9,-2404.89 5567.9,-1794.89 -1033.6,-1794.89 -1033.6,-2404.89 ; 1430.9,-2404.89 1430.9,-1794.89 ; 2697.9,-1998.23 2697.9,-1794.89 ; 3537.9,-1998.23 3537.9,-1794.89 ; 4159.9,-2411.39 4159.9,-2208.56
  text "TP20" at 2220,2049 h25
  text "TP21" at 1793,1764 h25
  text "TP22" at 2230,1682 h25
  text "TP1" at 1532,480 h25
  text "COMPONENTS MARKED 'DNP' SHOULD NOT BE POPULATED." at 411.4,-1589.89 h25
  text "ASSEMBLY VARIANT:" at 410.9,-1705.39 h25
  text ".VariantName" at 1446.9,-1705.39 h25
  text "ALL ARTWORK VIEWED FROM TOP SIDE" at -970.6,-1927.06 h25
  text "BOARD #:" at 1505.9,-1927.06 h25
  text ".PRJ_Number" at 2051.4,-1927.06 h25
  text "REV:" at 2895.9,-1927.06 h25
  text ".PCB_Rev" at 3187.4,-1927.06 h25
  text "SVN REV:" at 3733.9,-1927.06 h25
  text ".VersionControl_RevNumber" at 4239.9,-1927.06 h25
  text ".layer_Name" at -207.1,-2109.39 h25
  text "LAYER NAME =" at -977.1,-2116.39 h25
  text "TID #:" at 1510.9,-2127.06 h25
  text ".PRJ_Number" at 1881.4,-2127.06 h25
  text ".plot_File_Name" at -979.1,-2305.39 h25
  text "GENERATED    :" at 1507.9,-2335.73 h25
  text ".Print_Date" at 2377.4,-2335.73 h25
  text ".Print_Time" at 3106.4,-2335.73 h25
  text "TEXAS INSTRUMENTS" at 4370.9,-2335.73 h25
M6 Assembly Bottom:
  lines w6: -1034.6,-1998.73 5567.4,-1998.73 ; -1032.6,-2202.06 5567.4,-2202.06 ; 995.4,-1998.73 995.4,-1795.39 ; 1835.4,-1998.73 1835.4,-1795.39 ; 3102.4,-2405.39 3102.4,-1795.39 ; 3991.4,-2405.39 5566.9,-2405.39 5566.9,-1795.39 -1034.6,-1795.39 -1034.6,-2405.39 1562.4,-2405.39 5567.4,-2405.39 5567.4,-1795.39
  text "COMPONENTS MARKED 'DNP' SHOULD NOT BE POPULATED." at 5359.9,-1589.39 h25
  text ".VariantName" at 4315.9,-1705.39 h25
  text "ASSEMBLY VARIANT:" at 5354.9,-1705.39 h25
  text "Not in version control" at 514,-1922 h25
  text "SVN REV:" at 799.4,-1927.56 h25
  text ".PCB_Rev" at 1345.9,-1927.56 h25
  text "REV:" at 1637.4,-1927.56 h25
  text ".PRJ_Number" at 2481.9,-1927.56 h25
  text "BOARD #:" at 3027.4,-1927.56 h25
  text "PCB VIEWED FROM BOTTOM SIDE" at 5503.9,-1927.56 h25
  text "LAYER NAME =" at 5498.9,-2112.39 h25
  text ".Layer_Name" at 4725.9,-2119.39 h25
  text ".PRJ_Number" at 2478.6,-2122.06 h25
  text "TID #:" at 3004.1,-2127.06 h25
  text "IGNORE ->" at 1805.75,-2129.89 h25
  text ".Print_Time" at 1426.9,-2336.23 h25
  text ".Print_Date" at 2155.9,-2336.23 h25
  text "GENERATED    :" at 3025.4,-2336.23 h25
  text ".plot_File_Name" at 4698.4,-2336.23 h25
  text "PLOT NAME =" at 5503.9,-2336.23 h25
M9 Title Sheet:
  drawing of 54 lines, arcs and shapes, not listed
  text "1" at -2.26,6765.11 h70
  text "2" at 2493.4,6765.11 h70
  text "3" at 4982.74,6765.11 h70
  text "4" at 7489.41,6765.11 h70
  text "5" at 9988.4,6765.11 h70
  text "6" at 12493.4,6765.11 h70
  text "A" at -1158.6,5622.11 h70
  text "A" at 13641.4,5622.11 h70
  text "B" at -1158.6,3242.11 h70
  text "B" at 13641.4,3242.11 h70
  text "C" at -1158.6,867.11 h70
  text "C" at 13641.4,867.11 h70
  text "PROJECT TITLE:" at 10601.4,-993.89 h45
  text ".PRJ_Title" at 10595,-1118 h30
  text "DESIGNED FOR:" at 10601.4,-1294.89 h45
  text ".PRJ_Customer" at 10651.4,-1434.89 h70
  text "D" at -1158.6,-1502.89 h70
  text "D" at 13641.4,-1502.89 h70
  text "FILE NAME:" at 10601.4,-1594.89 h45
  text ".PCB_File_Name_No_Path" at 10932.9,-1720.39 h70
  text "Texas Instruments (TI) and/or its licensors do not warrant the accuracy or completeness of this specification" at 5631.9,-1876.73 h45
  text "ENGINEER:" at 10601.4,-1884.89 h45
  text "LAYOUT BY:" at 12106.4,-1884.89 h45
  text "or any information contained therein. TI and/or its licensors do not warrant that this design will meet" at 5586.91,-1989.4 h45
  text ".PRJ_Engineer" at 10651.4,-2039.88 h50
  text ".PCB_Layout" at 12156.9,-2039.88 h70
  text "the specifications, will be suitable for your application or fit for any particular purpose, or will operate in" at 5586.91,-2102.06 h45
  text "ALTIUM DESIGNER VERSION:" at 12106.4,-2194.89 h45
  text "an implementation. TI and/or its licensors do not warrant that the design is production worthy. You should" at 5586.91,-2214.73 h45
  text "completely validate and test your design implementation to confirm the system functionality for your application." at 5631.9,-2327.39 h45
  text ".print_Scale" at 10651.4,-2328.22 h70
  text ".Application_BuildNumber" at 12156.9,-2328.22 h70
  text "2" at 2493.4,-2534.89 h70
  text "3" at 4982.74,-2534.89 h70
  text "4" at 7489.41,-2534.89 h70
  text "5" at 9988.4,-2534.89 h70
  text "6" at 12493.4,-2534.89 h70
M10 Fab Notes:
  drawing of 228 lines, arcs and shapes, not listed
  text "DESIGN INFORMATION" at 11638.92,5538.61 h60
  text "(REFER ALSO ARRAY/PANEL PROFILING INFORMATION)" at 11277.36,5376.89 h60
  text "BOARD SIZE" at 10591.36,5372.61 h60
  text "100MM" at 11053.68,5244.79 h60
  text "X" at 11559.36,5244.79 h60
  text "75MM" at 11790.68,5244.79 h60
  text "Number of Layers :" at 10994.36,5047.61 h60
  text "4" at 12089.17,5037.61 h60
  text "MIN. TRACK WIDTH:" at 10994.36,4908.61 h60
  text "8" at 12090.6,4908.61 h60
  text "MIL" at 12245.36,4908.61 h60
  text "7.5" at 12049,4793.43 h60
  text "MIN. CLEARANCE:" at 10994.36,4776.61 h60
  text "MIL" at 12245.36,4776.61 h60
  text "7.874" at 11944,4646 h60
  text "MIN. VIA DRILL SIZE:" at 10994.36,4644.61 h60
  text "MIL" at 12245.36,4644.61 h60
  text "5.9055 MIL" at 11689.36,4502.9 h60
  text "MINIMUM ANNULAR RING" at 10665.13,4498.61 h60
  text "EXTERNAL" at 12397.36,4498.61 h60
  text "PER" at 10865.13,4380.61 h60
  text "IPC-D-275 CLASS 2 LEVEL C" at 11085.13,4380.61 h60
  text "MIL, HOLES" at 12573.36,4268.32 h60
  text "+/-" at 12180.9,4267.61 h60
  text "+/-" at 13034.9,4267.61 h60
  text "REGISTRATION TOLERANCES:" at 10665.13,4262.61 h60
  text "METAL" at 11864.9,4262.61 h60
  text "5" at 12441.1,4262.61 h60
  text "3" at 13274.1,4262.61 h60
  text "MIL" at 13390.36,4262.61 h60
  text "MATERIAL:" at 10590.36,4053.15 h60
  text "FR-4 High Tg" at 11576.8,3912.82 h60
  text "FR-408" at 11011.36,3904.25 h60
  text "X" at 11417.9,3904.61 h60
  text "OTHER" at 12499.36,3904.25 h60
  text "63 MIL (1.6mm) +/-10%" at 11331.46,3741.53 h60
  text "THICKNESS:" at 10665.13,3737.25 h60
  text "X" at 11203.3,3737.25 h60
  text "OTHER" at 12616.36,3737.25 h60
  text "TOLERANCE:" at 10665.13,3579.25 h60
  text "X" at 11504.43,3579.25 h60
  text "ANSI IPC-6012 TYPE 3 CLASS 2" at 11691.38,3579.25 h60
  text "OTHER +/-" at 11691.36,3423.25 h60
  text "BOW & TWIST:" at 10665.13,3266.25 h60
  text "X" at 11504.43,3266.25 h60
  text "ANSI IPC-6012 TYPE 3 CLASS 2" at 11691.38,3266.25 h60
  text "OTHER +/-" at 11691.36,3107.74 h60
  text "COPPER THICKNESS (FINISHED):" at 10590.36,2972.25 h60
  text "1.4MIL (1oz)" at 11470.36,2819.53 h60
  text "2MIL (1.4oz)" at 12237.36,2819.53 h60
  text "2.8MIL (2oz)" at 12964.36,2819.53 h60
  text "OUTER:" at 10947.36,2815.25 h60
  text "X" at 11341.9,2814.61 h60
  text "1.4MIL (1oz)" at 11470.36,2662.53 h60
  text "2.8MIL (2oz)" at 12237.36,2662.53 h60
  text "N/A" at 12963.9,2662.89 h60
  text "INNER SIGNAL:" at 10658.28,2658.25 h60
  text "X" at 11340.9,2656.61 h60
  text "DRILLING:" at 10590.36,2519.25 h60
  text "REFERENCE:" at 10665.13,2402.25 h60
  text "X" at 11313.36,2402.25 h60
  text "AS SHOWN" at 11500.36,2402.25 h60
  text "X" at 12214.36,2402.25 h60
  text "NC_DRILL FILES" at 12351.36,2402.25 h60
  text "PTH MIN COPPER THICKNESS:" at 10665.13,2244.25 h60
  text "X" at 12015.36,2244.25 h60
  text "1MIL" at 12152.36,2244.25 h60
  text "OTHER" at 12649.36,2244.25 h60
  text "BOARD FINISH:" at 10590.36,2085.25 h60
  text "SILKSCREEN:" at 10745.58,1967.25 h60
  text "X" at 11694.36,1967.25 h60
  text "TOP" at 11820.36,1967.25 h60
  text "X" at 12204.36,1967.25 h60
  text "BOTTOM" at 12331.36,1967.25 h60
  text "SILKSCREEN COLOR:" at 10745.58,1800.25 h60
  text "X" at 11693.32,1800.25 h60
  text "WHITE" at 11820.36,1800.25 h60
  text "OTHER" at 12331.36,1800.25 h60
  text "SOLDER RESIST COLOR:" at 10745.58,1630.25 h60
  text "X" at 11313.32,1471.05 h60
  text "GREEN" at 11440.36,1471.05 h60
  text "BLUE" at 12031.36,1471.05 h60
  text "OTHER" at 12569.36,1471.05 h60
  text "IMMERSION GOLD (ENIG)" at 11651.36,1282.53 h60
  text "ENEPIG" at 12988.9,1279.25 h60
  text "SURFACE FINISH:" at 10590.36,1278.25 h60
  text "X" at 11464.41,1278.25 h60
  text "IMM. TIN/SILVER OR EQUIV" at 10919.9,1121.25 h60
  text "OTHER" at 12351.36,1121.25 h60
  text "ARRAY/PANEL:" at 10590.36,942.25 h60
  text "CUT AND TRIM PER MECH LAYER 1" at 11651.36,937.96 h60
  text "N.C. ROUTE" at 11651.36,786.25 h60
  text "X" at 12330.36,786.25 h60
  text "V. SCORE" at 12517.36,786.25 h60
  text "CERTIFICATION:" at 10590.36,649.25 h60
  text "MATERIALS AND WORKMANSHIP FOR ALL PCBS" at 11315.36,649.25 h60
  text "TO MEET OR EXCEED THE REQUIREMENTS OF:" at 11315.36,551.25 h60
  text "X" at 10941.86,414.74 h60
  text "ANSI IPC-A-600F CLASS ->" at 11080.86,414.74 h60
  text "X" at 12719.92,414.74 h60
  text "2" at 12838.86,414.74 h60
  text "1" at 12523.86,413.25 h60
  text "3" at 13192.86,413.25 h60
  text "X" at 10943.92,255.25 h60
  text "UL 94V-0" at 11080.86,255.25 h60
  text "X" at 11755.92,255.25 h60
  text "RoHS" at 11892.86,255.25 h60
  text "OTHER" at 12537.26,255.25 h60
  text "PER ORDER" at 12934.32,255.25 h60
  text "NOTE :" at 4464.36,153.25 h60
  text "X" at 12566,128 h60
  text "VIA TENTING:" at 11807.9,121.61 h60
  text "ADDITIONAL REQUIREMENTS:" at 10590.36,114.25 h60
  text "YES" at 12357.57,112.53 h60
  text "NO" at 12722.37,107.3 h60
  text "Only 7.874 ,16 and 18mil VIAS are not tented." at 4742.36,24.25 h60
  text "MICROSECTION:" at 10665.13,-0.75 h60
  text "YES" at 11570.86,-0.75 h60
  text "IMPEDANCE CONTROL:" at 11829.9,-7.39 h60
  text "YES" at 12813.9,-8.39 h60
  text "X" at 13355.9,-15.39 h60
  text "NO" at 13189.37,-25.7 h60
  text "REQUIRED" at 12432.36,-156.9 h60
  text "BARE BOARD ELEC. TEST:" at 10665.13,-159.75 h60
  text "NONE" at 11970.86,-159.75 h60
  text "X" at 12305.36,-159.75 h60
  text "PER ORDER" at 13024.36,-159.75 h60
  text "MANUFACTURER'S UL:" at 10665.13,-316.75 h60
  text "RAIL" at 11830.86,-321.04 h60
  text "METAL" at 12322.67,-321.04 h60
  text "X" at 12697.9,-321.39 h60
  text "SILK" at 12834.36,-321.04 h60
M11 Gerber Information:
  lines w12: -1034.1,-2201.56 5565.9,-2201.56 ; -1034.1,-1998.23 5567.9,-1998.23 ; -1034.1,-1794.89 -1034.1,-2404.89 2970.9,-2404.89 5567.9,-2404.89 5567.9,-1794.89 -1033.6,-1794.89 -1033.6,-2404.89 ; 1430.9,-2404.89 1430.9,-1794.89 ; 2697.9,-1998.23 2697.9,-1794.89 ; 3537.9,-1998.23 3537.9,-1794.89 ; 4159.9,-2411.39 4159.9,-2208.56
  text ".PRJ_Number" at 1986.18,-1921.49 h40
  text "BOARD #:" at 1505.9,-1927.06 h60
  text "REV:" at 2895.9,-1927.06 h60
  text ".PCB_Rev" at 3187.4,-1927.06 h60
  text "SVN REV:" at 3733.9,-1927.06 h60
  text ".VersionControl_RevNumber" at 4239.9,-1927.06 h60
  text "ALL ARTWORK VIEWED FROM TOP SIDE" at -971.6,-1933.06 h60
  text "LAYER NAME =" at -973.1,-2116.39 h60
  text ".PRJ_Number" at 1866.18,-2131.49 h40
  text "TID #:" at 1500.9,-2137.06 h60
  text ".plot_File_Name" at -981.1,-2315.39 h60
  text "GENERATED    :" at 1507.9,-2335.73 h60
  text ".Print_Date" at 2377.4,-2335.73 h60
  text ".Print_Time" at 3106.4,-2335.73 h60
  text "TEXAS INSTRUMENTS" at 4370.9,-2335.73 h60
M12 Stackup:
  lines w6: 10617.9,6188.61 13167.9,6188.61 ; 10617.9,6293.01 13167.9,6293.01 ; 10557.9,5703.61 ccw(c10591.9,5703.61) 10591.9,5669.61 13193.9,5669.61 ccw(c13193.9,5703.61) 13227.9,5703.61 13227.9,6409.61 ccw(c13193.9,6409.61) 13193.9,6443.61 10591.9,6443.61 ccw(c10591.9,6409.61) 10557.9,6409.61 10557.9,5703.61
  text "Layer Stack Up Detail for: TIDA-01035-E1" at 10586.18,6328.51 h57
  text "Layer" at 10617.9,6254.01 h24
  text "Gerber" at 11513.71,6254.01 h24
  text "Copper" at 12077.23,6254.01 h24
  text "Dielectric" at 12679.94,6254.01 h24
  text "Name" at 10617.9,6206.01 h24
  text "Document" at 11513.71,6206.01 h24
  text "Thickness" at 12077.23,6206.01 h24
  text "Material" at 12679.94,6206.01 h24
  text "Top Solder Mask" at 10632.9,6114.61 h34
  text "(.GTS)" at 11513.71,6113.05 h34
  text "Solder Resist" at 12679.94,6113.05 h34
  text "Top Layer" at 10627.9,6019.61 h34
  text "(.GTL)" at 11513.71,6016.3 h34
  text "1.4mil" at 12077.23,6016.3 h34
  text "FR4-High Tg" at 12708.9,6015.61 h34
  text "GND" at 10627.9,5956.61 h34
  text "FR4-High Tg" at 12707.9,5952.61 h34
  text "1.4mil" at 12076.23,5951.3 h34
  text "(.G1)" at 11514.71,5939.3 h34
  text "1.4mil" at 12075.23,5876.3 h34
  text "FR4-High Tg" at 12707.9,5876.61 h34
  text "PWR" at 10627.9,5872.61 h34
  text "(.G2)" at 11514.71,5867.3 h34
  text "FR4-High Tg" at 12713.9,5790.61 h34
  text "Bottom Layer" at 10622.9,5789.61 h34
  text "(.GBL)" at 11521.9,5785.61 h34
  text "1.4mil" at 12081.9,5779.61 h34
  text "Solder Resist" at 12673.9,5712.61 h34
  text "(.GBS)" at 11518.9,5705.61 h34
  text "Bottom Solder Mask" at 10627.9,5704.61 h34
M13 Component Bodies Top:
  text ".Layer_Name" at -165.1,-2129.89 h60
M14 Component Bodies Bottom:
  text ".Layer_Name" at -165.1,-2129.89 h60
M15 Courtyards Top:
  text ".Layer_Name" at -165.1,-2129.89 h60
M16 Courtyards Bottom:
  text ".Layer_Name" at -165.1,-2129.89 h60
Drill Drawing:
  text ".legend" at 4485,987 h60
  text "Drill Table" at 4478.9,842.61 h60
  text "FOR 7.874MIL DRILL +0/-7.874MIL" at 4478.9,678.61 h60
  text "FOR 12MIL DRILL +0/-12MIL" at 4478.9,573.61 h60
  text "FOR 16MIL DRILL +0/-16MIL" at 4478.9,488.61 h60
  text "FOR PTH DRILL +/-3MIL" at 4485.18,375.51 h60
  text "FOR NPTH DRILL +/-2MIL" at 4483.18,280.51 h60
  text ".layer_Name" at -60.1,-2113.39 h60

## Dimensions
0,0 to 3937.01,0 on M2 Board Dimensions
0,0 to 0,2952.76 on M2 Board Dimensions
